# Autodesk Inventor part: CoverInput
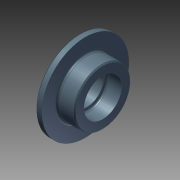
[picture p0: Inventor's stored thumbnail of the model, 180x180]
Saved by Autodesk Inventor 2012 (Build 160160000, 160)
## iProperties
Part Number: CoverInput
Document SubType Name: Modeling
Created: 2003-11
Designer: ales
Manufacturer: Standard
Standards Organization: Custom
Density: 1 g/cm^3
Material: Default
Control State: 0
Master: False
Checked Out: False
Shininess: 64.0
Length Units: 11269
Angle Units: 11279
Time Units: 11290
Mass Units: 11283
Length Display Precision: 3
Angle Display Precision: 2
Compacted: True
Density: 0.0
Volumn: 0.0
Area: 0.0
PropertySet Name: Model Information
Author: ales
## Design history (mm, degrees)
sketch "Sketch1"
  geometry: L1 (0, 0)-(25.981, 0); L2 (0, 15.5)-(10, 15.5); L3 (10, 15.5)-(10, 18.5); L4 (10, 18.5)-(25, 18.5); L5 (0, 22.5)-(0, 15.5); L6 (2, 22.5)-(2, 42.5); L7 (2, 42.5)-(8, 42.5); L8 (8, 42.5)-(8, 27.5); L9 (8, 27.5)-(25, 27.5); L10 (25, 27.5)-(25, 18.5); L11 (0, 22.5)-(2, 22.5)
  constraints: 22 end point, 6 perpendicular, 1 horizontal, 1 parallel, 1 point on line, 1 vertical, 1 other
  dimensions: "d0" = 31 diameter of L2 L1; "d2" = 37 diameter of L4 L1; "d5" = 15 distance of L3.end L4.end; "d7" = 6 distance of L6.end L7.end; "d9" = 85 diameter of L7 L1; "d11" = 55 diameter of L9 L1; "d12" = 45 diameter of L11 L1; "d13" = 25 distance between parallel lines of L10 L5; "d14" = 8 distance between parallel lines of L5 L8
revolve "Revolution1" sketch "Sketch1" stored, may be unused: angle "d6" = 90 deg
fillet "Fillet1" dims "d10" = 2
chamfer "Chamfer2" distance "d32" = 1; stored, may be unused: second distance "d33" = 2, angle "d34" = 45 deg
body "Solid1"
